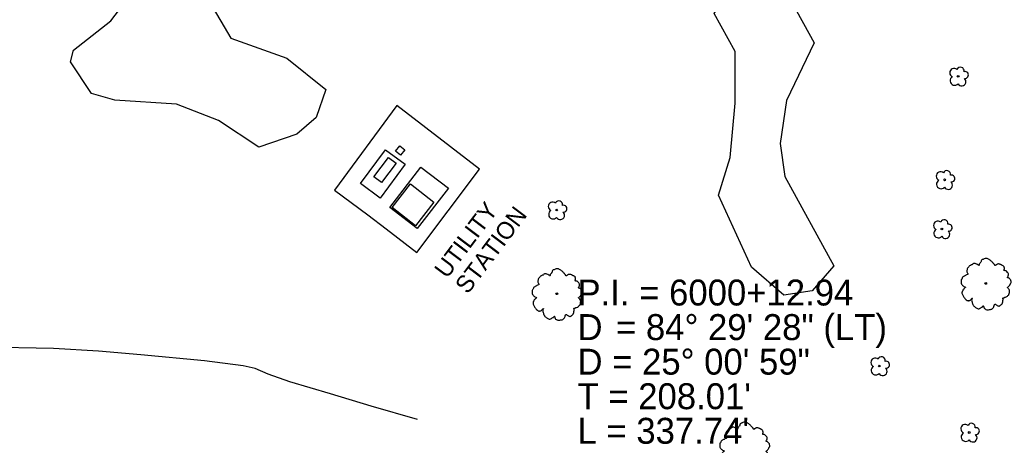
# Model space of a CAD drawing. Extents: x 2132221 to 2141942, y 535736 to 547298.
# Drawn here: x 2138626.8 to 2138913.4, y 541120.6 to 541243.7 of the extents above; entities that cross this region are included whole.
import ezdxf

# ---------------------------------------------------------------- set-up
doc = ezdxf.new("R2010")
doc.units = 0
for name, color, linetype in [('RD_EX_Bldg', 7, 'Continuous'), ('RD_EX_Conc', 7, 'Continuous'), ('RD_EX_Fence_ChLk', 7, 'Continuous'), ('RD_EX_GuardRail', 7, 'Continuous'), ('RD_EX_Misc', 7, 'Continuous'), ('RD_EX_UT', 7, 'Continuous'), ('RD_EX_UT_txCode', 7, 'Continuous'), ('RD_EX_VEG', 7, 'Continuous'), ('RD_HC_Data', 7, 'Continuous')]:
    doc.layers.add(name, color=color, linetype=linetype)

msp = doc.modelspace()

# ---------------------------------------------------------------- linework, layer by layer
at = {"layer": 'RD_EX_Bldg'}
msp.add_lwpolyline([(2138739.71, 541196.21), (2138746.51, 541190.89), (2138741.18, 541184.07), (2138734.38, 541189.39)], close=True, dxfattribs=at)
at = {"layer": 'RD_EX_Conc'}
for points in [[(2138738.16, 541201.87), (2138730.95, 541192.08), (2138725.26, 541196.28), (2138732.47, 541206.07)], [(2138750.66, 541194.94), (2138741.69, 541183.27), (2138733.7, 541189.38), (2138742.67, 541201.04)]]:
    msp.add_lwpolyline(points, close=True, dxfattribs=at)
at = {"layer": 'RD_EX_Fence_ChLk'}
msp.add_lwpolyline([(2138727.42, 541187.2), (2138732.7, 541183.18), (2138741.58, 541176.3), (2138759.63, 541200.47), (2138735.76, 541218.85), (2138717.72, 541194.41)], close=True, dxfattribs=at)
at = {"layer": 'RD_EX_GuardRail'}
msp.add_lwpolyline([(2138741.71, 541128.04), (2138728.38, 541131.85), (2138716.59, 541135.4), (2138704.82, 541138.92), (2138698.54, 541141.16), (2138694.8, 541142.81), (2138691.38, 541143.5), (2138680.12, 541145.01), (2138661.79, 541146.7), (2138649.51, 541147.76), (2138636.49, 541148.52), (2138616.27, 541148.94)], dxfattribs=at)
at = {"layer": 'RD_EX_Misc'}
msp.add_lwpolyline([(2138736.62, 541207.22), (2138738.04, 541206.07), (2138736.8, 541204.53), (2138735.38, 541205.67)], close=True, dxfattribs=at)
at = {"layer": 'RD_EX_UT'}
msp.add_lwpolyline([(2138729.09, 541198.24), (2138733.32, 541203.85), (2138735.56, 541202.16), (2138731.33, 541196.55)], close=True, dxfattribs=at)
at = {"layer": 'RD_EX_VEG'}
for points in [[(2138672.04, 541219.22), (2138654.27, 541220.43), (2138647.51, 541222.35), (2138641.43, 541231.55), (2138642.24, 541234.89), (2138653.09, 541243.4), (2138660.93, 541253.77), (2138668.05, 541260.71), (2138676.75, 541261.51), (2138681.72, 541248.68), (2138687.75, 541238.32), (2138703.98, 541232.55), (2138715.27, 541223.52), (2138712.43, 541215.35), (2138706.84, 541210.57), (2138695.9, 541206.78), (2138684.17, 541214.49)], [(2138849.83, 541249.02), (2138856.47, 541236.98), (2138848.45, 541220.33), (2138846.59, 541207.86), (2138847.93, 541198.35), (2138862.11, 541172.49), (2138855.83, 541165.22), (2138847.68, 541164.01), (2138838.36, 541172.12), (2138828.8, 541192.96), (2138832.14, 541203.83), (2138833.56, 541219.59), (2138833.6, 541234.45), (2138827.49, 541245.51), (2138831.8, 541251.7), (2138836.89, 541253.42), (2138840.94, 541253.44)]]:
    msp.add_lwpolyline(points, close=True, dxfattribs=at)
for centre, radius in [((2138898.07, 541227.3), 0.25), ((2138894.15, 541197.36), 0.25), ((2138781.99, 541188.63), 0.25), ((2138893.37, 541183.15), 0.25), ((2138906.04, 541167.38), 0.25), ((2138906.02, 541167.38), 0.0001), ((2138782.02, 541164.39), 0.25), ((2138781.99, 541164.38), 0.0001), ((2138875.26, 541143.49), 0.25), ((2138901.26, 541124.26), 0.25)]:
    msp.add_circle(centre, radius, dxfattribs=at)
for centre, radius, start, end in [((2138896.9, 541228.35), 1.26, 49.0921, 247.3743), ((2138898.72, 541228.88), 1.08, 347.6166, 157.3963), ((2138900.03, 541227.69), 0.995, 261.4029, 104.687), ((2138897.06, 541226.04), 1.32, 119.5229, 318.3992), ((2138899.11, 541225.76), 1.22, 209.207, 50.7449), ((2138892.98, 541198.41), 1.26, 49.0921, 247.3743), ((2138894.8, 541198.94), 1.08, 347.6166, 157.3963), ((2138893.14, 541196.1), 1.32, 119.5229, 318.3992), ((2138895.19, 541195.82), 1.22, 209.207, 50.7449), ((2138896.11, 541197.75), 0.995, 261.4029, 104.687), ((2138780.81, 541189.67), 1.26, 49.0921, 247.3743), ((2138782.64, 541190.2), 1.08, 347.6166, 157.3963), ((2138780.98, 541187.36), 1.32, 119.5229, 318.3992), ((2138783.03, 541187.08), 1.22, 209.207, 50.7449), ((2138783.95, 541189.01), 0.995, 261.4029, 104.687), ((2138892.2, 541184.19), 1.26, 49.0921, 247.3743), ((2138894.02, 541184.73), 1.08, 347.6166, 157.3963), ((2138892.36, 541181.89), 1.32, 119.5229, 318.3992), ((2138894.41, 541181.61), 1.22, 209.207, 50.7449), ((2138895.33, 541183.53), 0.995, 261.4029, 104.687), ((2138874.09, 541144.53), 1.26, 49.0921, 247.3743), ((2138875.91, 541145.07), 1.08, 347.6166, 157.3963), ((2138874.25, 541142.22), 1.32, 119.5229, 318.3992), ((2138876.3, 541141.94), 1.22, 209.207, 50.7449), ((2138877.22, 541143.87), 0.995, 261.4029, 104.687), ((2138900.09, 541125.31), 1.26, 49.0921, 247.3743), ((2138901.91, 541125.84), 1.08, 347.6166, 157.3963), ((2138903.22, 541124.65), 0.995, 261.4029, 104.687), ((2138900.26, 541123), 1.32, 119.5229, 318.3992), ((2138902.3, 541122.72), 1.22, 209.207, 50.7449)]:
    msp.add_arc(centre, radius, start, end, dxfattribs=at)
for points in [[(2138911.4, 541172.14), (2138911.22, 541172.37), (2138910.93, 541172.55), (2138910.68, 541172.66), (2138910.48, 541172.78), (2138910.25, 541172.87), (2138909.92, 541172.98), (2138909.62, 541173.01), (2138909.35, 541172.93), (2138909.15, 541172.81), (2138908.91, 541172.66), (2138908.79, 541172.55), (2138908.68, 541172.62), (2138908.6, 541172.75), (2138908.49, 541172.98), (2138908.32, 541173.17), (2138908.15, 541173.35), (2138907.89, 541173.59), (2138907.65, 541173.85), (2138907.43, 541174.02), (2138907.17, 541174.22), (2138906.83, 541174.41), (2138906.5, 541174.58), (2138906.11, 541174.64), (2138905.59, 541174.5), (2138905.25, 541174.35), (2138904.97, 541174.29), (2138904.74, 541173.88), (2138904.6, 541173.51), (2138904.47, 541173.36), (2138904.21, 541173.02), (2138904.11, 541172.79), (2138904.05, 541172.56), (2138903.98, 541172.6), (2138903.69, 541172.84), (2138903.41, 541173), (2138902.96, 541173.16), (2138902.64, 541173.17), (2138902.33, 541173.02), (2138902.06, 541172.8), (2138901.84, 541172.74), (2138901.59, 541172.61), (2138901.52, 541172.58), (2138901.25, 541172.4), (2138900.98, 541172.02), (2138900.74, 541171.76), (2138900.66, 541171.52), (2138900.63, 541171.29), (2138900.57, 541170.99), (2138900.67, 541170.55), (2138900.82, 541170.24), (2138900.94, 541170.07), (2138900.45, 541169.86), (2138900.16, 541169.66), (2138899.78, 541169.49), (2138899.73, 541169.43), (2138899.34, 541169.15), (2138899.21, 541168.82), (2138898.98, 541168.51), (2138898.93, 541168.23), (2138898.9, 541167.82), (2138898.95, 541167.43), (2138899.2, 541166.98), (2138899.49, 541166.7), (2138900.01, 541166.4), (2138900.23, 541166.27), (2138900.09, 541166.17), (2138899.83, 541165.89), (2138899.52, 541165.61), (2138899.38, 541165.28), (2138899.24, 541165.02), (2138899.16, 541164.74), (2138899.22, 541164.34), (2138899.43, 541164), (2138899.61, 541163.59), (2138899.86, 541163.2), (2138900.18, 541162.82), (2138900.7, 541162.48), (2138900.97, 541162.36), (2138901.17, 541162.41), (2138901.58, 541162.51), (2138901.71, 541162.7), (2138902.17, 541163.09), (2138902.11, 541162.9), (2138901.97, 541162.53), (2138902.09, 541161.96), (2138902.23, 541161.55), (2138902.44, 541161.1), (2138902.59, 541160.83), (2138902.97, 541160.53), (2138903.28, 541160.3), (2138903.62, 541160.11), (2138904.03, 541160.08), (2138904.35, 541160.14), (2138904.58, 541160.29), (2138904.91, 541160.48), (2138905.07, 541160.57)], [(2138787.38, 541169.15), (2138787.19, 541169.38), (2138786.9, 541169.55), (2138786.66, 541169.67), (2138786.45, 541169.78), (2138786.22, 541169.88), (2138785.89, 541169.98), (2138785.59, 541170.01), (2138785.32, 541169.94), (2138785.12, 541169.82), (2138784.89, 541169.67), (2138784.76, 541169.55), (2138784.66, 541169.63), (2138784.57, 541169.76), (2138784.46, 541169.99), (2138784.29, 541170.17), (2138784.12, 541170.36), (2138783.87, 541170.6), (2138783.63, 541170.86), (2138783.41, 541171.02), (2138783.15, 541171.23), (2138782.8, 541171.42), (2138782.47, 541171.59), (2138782.09, 541171.64), (2138781.57, 541171.51), (2138781.23, 541171.36), (2138780.94, 541171.3), (2138780.71, 541170.89), (2138780.57, 541170.52), (2138780.44, 541170.37), (2138780.18, 541170.03), (2138780.08, 541169.8), (2138780.02, 541169.57), (2138779.95, 541169.61), (2138779.66, 541169.85), (2138779.39, 541170.01), (2138778.93, 541170.17), (2138778.61, 541170.18), (2138778.31, 541170.03), (2138778.03, 541169.81), (2138777.82, 541169.75), (2138777.57, 541169.62), (2138777.49, 541169.59), (2138777.22, 541169.4), (2138776.96, 541169.03), (2138776.72, 541168.77), (2138776.64, 541168.53), (2138776.61, 541168.3), (2138776.54, 541168), (2138776.65, 541167.55), (2138776.8, 541167.25), (2138776.91, 541167.08), (2138776.43, 541166.87), (2138776.14, 541166.67), (2138775.76, 541166.49), (2138775.7, 541166.44), (2138775.32, 541166.16), (2138775.18, 541165.83), (2138774.96, 541165.52), (2138774.91, 541165.24), (2138774.87, 541164.83), (2138774.93, 541164.44), (2138775.18, 541163.99), (2138775.46, 541163.71), (2138775.98, 541163.41), (2138776.21, 541163.27), (2138776.06, 541163.17), (2138775.8, 541162.9), (2138775.49, 541162.61), (2138775.35, 541162.28), (2138775.22, 541162.02), (2138775.14, 541161.74), (2138775.19, 541161.35), (2138775.41, 541161.01), (2138775.58, 541160.59), (2138775.83, 541160.21), (2138776.15, 541159.83), (2138776.67, 541159.49), (2138776.95, 541159.37), (2138777.14, 541159.42), (2138777.56, 541159.52), (2138777.69, 541159.71), (2138778.15, 541160.1), (2138778.08, 541159.91), (2138777.95, 541159.54), (2138778.06, 541158.97), (2138778.21, 541158.56), (2138778.42, 541158.11), (2138778.57, 541157.84), (2138778.94, 541157.54), (2138779.25, 541157.31), (2138779.6, 541157.12), (2138780, 541157.09), (2138780.32, 541157.14), (2138780.56, 541157.29), (2138780.89, 541157.49), (2138781.05, 541157.57)], [(2138905.07, 541160.57), (2138905.15, 541160.74), (2138905.3, 541160.95), (2138905.33, 541160.87), (2138905.42, 541160.71), (2138905.51, 541160.42), (2138905.61, 541160.21), (2138905.85, 541159.99), (2138906.11, 541159.85), (2138906.61, 541159.71), (2138907.15, 541159.83), (2138907.63, 541159.9), (2138907.92, 541160.06), (2138908.05, 541160.25), (2138908.4, 541160.61), (2138908.45, 541160.92), (2138908.51, 541161.04), (2138908.73, 541161.39), (2138908.82, 541161.37), (2138909.04, 541161.2), (2138909.39, 541161.01), (2138909.67, 541160.89), (2138909.95, 541160.84), (2138910.16, 541160.94), (2138910.44, 541161.23), (2138910.77, 541161.46), (2138910.83, 541161.62), (2138910.87, 541161.8), (2138910.97, 541161.99), (2138910.98, 541162.2), (2138911.02, 541162.37), (2138911.03, 541162.51), (2138911.05, 541162.71), (2138911.02, 541162.92), (2138910.96, 541163.07), (2138911.04, 541163.2), (2138911.28, 541163.23), (2138911.39, 541163.26), (2138911.57, 541163.39), (2138911.98, 541163.47), (2138912.31, 541163.7), (2138912.59, 541164.02), (2138912.76, 541164.25), (2138912.86, 541164.54), (2138912.91, 541164.86), (2138912.95, 541165.07), (2138912.93, 541165.28), (2138912.8, 541165.61), (2138912.66, 541165.82), (2138912.43, 541166.08), (2138912.33, 541166.26), (2138912.38, 541166.28), (2138912.49, 541166.38), (2138912.7, 541166.57), (2138912.98, 541166.93), (2138913.24, 541167.37), (2138913.26, 541167.39), (2138913.38, 541167.63), (2138913.37, 541167.94), (2138913.33, 541168.13), (2138913.28, 541168.36), (2138913.13, 541168.56), (2138912.93, 541168.78), (2138912.71, 541168.95), (2138912.5, 541169.03), (2138912.29, 541169.08), (2138912.35, 541169.23), (2138912.5, 541169.51), (2138912.57, 541169.65), (2138912.6, 541169.88), (2138912.6, 541170.18), (2138912.38, 541170.59), (2138911.91, 541171), (2138911.56, 541171.09), (2138911.33, 541171.08), (2138911.38, 541171.2), (2138911.39, 541171.48), (2138911.46, 541171.67), (2138911.43, 541171.89), (2138911.4, 541172.07), (2138911.37, 541172.17)], [(2138781.05, 541157.57), (2138781.13, 541157.75), (2138781.28, 541157.95), (2138781.31, 541157.88), (2138781.39, 541157.72), (2138781.48, 541157.43), (2138781.58, 541157.22), (2138781.82, 541156.99), (2138782.08, 541156.86), (2138782.59, 541156.72), (2138783.12, 541156.83), (2138783.6, 541156.9), (2138783.89, 541157.07), (2138784.02, 541157.26), (2138784.37, 541157.61), (2138784.42, 541157.93), (2138784.48, 541158.05), (2138784.71, 541158.4), (2138784.79, 541158.38), (2138785.02, 541158.21), (2138785.36, 541158.02), (2138785.64, 541157.9), (2138785.92, 541157.85), (2138786.14, 541157.95), (2138786.42, 541158.24), (2138786.74, 541158.47), (2138786.8, 541158.63), (2138786.85, 541158.8), (2138786.94, 541158.99), (2138786.95, 541159.21), (2138786.99, 541159.38), (2138787, 541159.52), (2138787.03, 541159.72), (2138787, 541159.93), (2138786.93, 541160.07), (2138787.01, 541160.21), (2138787.26, 541160.24), (2138787.37, 541160.27), (2138787.55, 541160.4), (2138787.96, 541160.47), (2138788.29, 541160.71), (2138788.57, 541161.03), (2138788.73, 541161.25), (2138788.83, 541161.55), (2138788.88, 541161.87), (2138788.93, 541162.08), (2138788.9, 541162.29), (2138788.77, 541162.61), (2138788.64, 541162.83), (2138788.4, 541163.09), (2138788.3, 541163.27), (2138788.36, 541163.29), (2138788.47, 541163.39), (2138788.67, 541163.57), (2138788.95, 541163.93), (2138789.22, 541164.38), (2138789.23, 541164.4), (2138789.35, 541164.64), (2138789.35, 541164.94), (2138789.3, 541165.14), (2138789.26, 541165.37), (2138789.11, 541165.57), (2138788.9, 541165.79), (2138788.68, 541165.96), (2138788.47, 541166.04), (2138788.26, 541166.08), (2138788.32, 541166.24), (2138788.47, 541166.52), (2138788.55, 541166.66), (2138788.58, 541166.89), (2138788.57, 541167.19), (2138788.36, 541167.6), (2138787.88, 541168.01), (2138787.53, 541168.1), (2138787.3, 541168.09), (2138787.36, 541168.21), (2138787.37, 541168.49), (2138787.43, 541168.68), (2138787.4, 541168.9), (2138787.38, 541169.07), (2138787.34, 541169.18)], [(2138841.62, 541124.74), (2138841.44, 541124.98), (2138841.14, 541125.15), (2138840.9, 541125.27), (2138840.69, 541125.38), (2138840.47, 541125.48), (2138840.14, 541125.58), (2138839.84, 541125.61), (2138839.57, 541125.54), (2138839.37, 541125.42), (2138839.13, 541125.27), (2138839, 541125.15), (2138838.9, 541125.23), (2138838.82, 541125.35), (2138838.7, 541125.59), (2138838.53, 541125.77), (2138838.36, 541125.96), (2138838.11, 541126.2), (2138837.87, 541126.45), (2138837.65, 541126.62), (2138837.39, 541126.83), (2138837.05, 541127.02), (2138836.72, 541127.19), (2138836.33, 541127.24), (2138835.81, 541127.11), (2138835.47, 541126.96), (2138835.19, 541126.9), (2138834.96, 541126.49), (2138834.82, 541126.12), (2138834.69, 541125.97), (2138834.43, 541125.62), (2138834.33, 541125.4), (2138834.26, 541125.17), (2138834.2, 541125.21), (2138833.91, 541125.45), (2138833.63, 541125.6), (2138833.18, 541125.76), (2138832.86, 541125.78), (2138832.55, 541125.63), (2138832.28, 541125.41), (2138832.06, 541125.35), (2138831.81, 541125.22), (2138831.74, 541125.19), (2138831.46, 541125), (2138831.2, 541124.62), (2138830.96, 541124.37), (2138830.88, 541124.13), (2138830.85, 541123.9), (2138830.79, 541123.6), (2138830.89, 541123.15), (2138831.04, 541122.85), (2138831.16, 541122.68), (2138830.67, 541122.47), (2138830.38, 541122.27), (2138830, 541122.09), (2138829.94, 541122.04), (2138829.56, 541121.76), (2138829.42, 541121.43), (2138829.2, 541121.12), (2138829.15, 541120.84), (2138829.12, 541120.43), (2138829.17, 541120.04), (2138829.42, 541119.59), (2138829.71, 541119.31), (2138830.23, 541119.01), (2138830.45, 541118.87), (2138830.31, 541118.77), (2138830.05, 541118.5), (2138829.73, 541118.21), (2138829.6, 541117.88), (2138829.46, 541117.62), (2138829.38, 541117.34), (2138829.43, 541116.95), (2138829.65, 541116.61), (2138829.83, 541116.19), (2138830.08, 541115.81), (2138830.4, 541115.43), (2138830.91, 541115.09), (2138831.19, 541114.97), (2138831.39, 541115.01), (2138831.8, 541115.12), (2138831.93, 541115.31), (2138832.39, 541115.7), (2138832.33, 541115.51), (2138832.19, 541115.14), (2138832.31, 541114.57), (2138832.45, 541114.16), (2138832.66, 541113.71), (2138832.81, 541113.43), (2138833.19, 541113.14), (2138833.49, 541112.91), (2138833.84, 541112.72), (2138834.25, 541112.69), (2138834.57, 541112.74), (2138834.8, 541112.89), (2138835.13, 541113.09), (2138835.29, 541113.17)], [(2138835.29, 541113.17), (2138835.37, 541113.35), (2138835.52, 541113.55), (2138835.55, 541113.48), (2138835.63, 541113.32), (2138835.73, 541113.03), (2138835.82, 541112.82), (2138836.06, 541112.59), (2138836.32, 541112.46), (2138836.83, 541112.31), (2138837.37, 541112.43), (2138837.85, 541112.5), (2138838.14, 541112.67), (2138838.27, 541112.86), (2138838.62, 541113.21), (2138838.67, 541113.53), (2138838.72, 541113.65), (2138838.95, 541114), (2138839.04, 541113.97), (2138839.26, 541113.81), (2138839.61, 541113.61), (2138839.89, 541113.5), (2138840.17, 541113.45), (2138840.38, 541113.55), (2138840.66, 541113.84), (2138840.99, 541114.07), (2138841.05, 541114.23), (2138841.09, 541114.4), (2138841.19, 541114.59), (2138841.19, 541114.8), (2138841.24, 541114.98), (2138841.24, 541115.12), (2138841.27, 541115.31), (2138841.24, 541115.53), (2138841.18, 541115.67), (2138841.25, 541115.81), (2138841.5, 541115.84), (2138841.61, 541115.87), (2138841.79, 541116), (2138842.2, 541116.07), (2138842.53, 541116.31), (2138842.81, 541116.63), (2138842.98, 541116.85), (2138843.08, 541117.15), (2138843.13, 541117.47), (2138843.17, 541117.68), (2138843.14, 541117.89), (2138843.02, 541118.21), (2138842.88, 541118.43), (2138842.65, 541118.69), (2138842.55, 541118.87), (2138842.6, 541118.88), (2138842.71, 541118.99), (2138842.91, 541119.17), (2138843.19, 541119.53), (2138843.46, 541119.98), (2138843.48, 541120), (2138843.59, 541120.24), (2138843.59, 541120.54), (2138843.54, 541120.74), (2138843.5, 541120.97), (2138843.35, 541121.17), (2138843.15, 541121.39), (2138842.92, 541121.56), (2138842.71, 541121.64), (2138842.5, 541121.68), (2138842.56, 541121.84), (2138842.72, 541122.12), (2138842.79, 541122.25), (2138842.82, 541122.48), (2138842.81, 541122.78), (2138842.6, 541123.2), (2138842.12, 541123.61), (2138841.77, 541123.69), (2138841.54, 541123.69), (2138841.6, 541123.81), (2138841.61, 541124.09), (2138841.67, 541124.28), (2138841.65, 541124.49), (2138841.62, 541124.67), (2138841.59, 541124.78)]]:
    msp.add_spline(points, degree=3, dxfattribs=at)

# ---------------------------------------------------------------- texts
at = {"layer": 'RD_EX_UT_txCode'}
for s, p in [('UTILITY', (2138750.26, 541168.55)), ('STATION', (2138756.25, 541164.04))]:
    msp.add_text(s, height=5, rotation=53.0009, dxfattribs=at).set_placement(p)
at = {"layer": 'RD_HC_Data'}
for s, p in [('P.I. = 6000+12.94', (2138788, 541161)), ('D', (2138788, 541151)), ('    = 84%%d 29\' 28" (LT)', (2138788, 541151)), ('D = 25%%d 00\' 59"', (2138788, 541141)), ("T = 208.01'", (2138788, 541131)), ("L = 337.74'", (2138788, 541121))]:
    msp.add_text(s, height=7.5, dxfattribs=at).set_placement(p)

doc.saveas('drawing.dxf')
